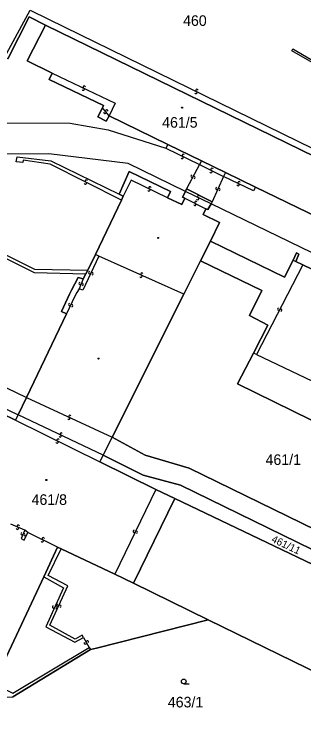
# Model space of a CAD drawing. Extents: x -600309 to -598967, y -1161267 to -1160292.
# Drawn here: x -599975.6 to -599929.1, y -1160957.9 to -1160844.2 of the extents above; entities that cross this region are included whole.
import ezdxf

# ---------------------------------------------------------------- set-up
doc = ezdxf.new("R2010")
doc.units = 0
for name, color, linetype in [('Level 1', 7, 'Continuous'), ('Level 13', 7, 'Continuous'), ('Level 3', 7, 'Continuous'), ('Level 4', 7, 'Continuous'), ('Level 5', 7, 'Continuous'), ('Level 60', 7, 'Continuous')]:
    doc.layers.add(name, color=color, linetype=linetype)

msp = doc.modelspace()

# ---------------------------------------------------------------- linework, layer by layer
at = {"layer": 'Level 1'}
for points in [[(-599970.57, -1160845.99), (-599973.21, -1160844.68), (-599976.65, -1160851.41), (-599979.13, -1160850.22)], [(-599969.49, -1160853.68), (-599973.54, -1160851.74), (-599970.57, -1160845.99)], [(-599922.74, -1160869.32), (-599970.57, -1160845.99)], [(-599969.49, -1160853.68), (-599969.98, -1160854.72), (-599961.24, -1160858.9), (-599961.41, -1160859.24)], [(-599961.41, -1160859.24), (-599962.16, -1160860.72), (-599960.84, -1160861.38), (-599960.35, -1160860.54)], [(-599960.35, -1160860.54), (-599950.92, -1160865.13)], [(-599950.92, -1160865.13), (-599945.53, -1160867.75)], [(-599945.53, -1160867.75), (-599941.67, -1160869.63)], [(-599950.95, -1160873.68), (-599950.5, -1160872.69), (-599957.14, -1160869.49), (-599958.73, -1160873.14)], [(-599941.67, -1160869.63), (-599936.85, -1160871.97)], [(-599948.2, -1160873.77), (-599948.56, -1160873.59), (-599948.1, -1160872.66)], [(-599948.1, -1160872.66), (-599947.91, -1160872.28)], [(-599947.91, -1160872.28), (-599943.8, -1160874.32)], [(-599936.85, -1160871.97), (-599926.79, -1160876.87)], [(-599958.73, -1160873.14), (-599958.07, -1160873.44)], [(-599958.37, -1160874.05), (-599958.07, -1160873.44)], [(-599950.95, -1160873.68), (-599948.66, -1160874.75), (-599948.2, -1160873.77)], [(-599962.53, -1160882.8), (-599958.37, -1160874.05)], [(-599944.79, -1160875.44), (-599944.49, -1160875.59), (-599943.98, -1160874.65)], [(-599943.8, -1160874.32), (-599943.98, -1160874.65)], [(-599944.79, -1160875.44), (-599945.23, -1160876.39), (-599942.61, -1160877.68), (-599944.04, -1160880.67)], [(-599945.66, -1160883.81), (-599944.04, -1160880.67)], [(-599944.04, -1160880.67), (-599932.19, -1160886.44), (-599930.79, -1160883.69)], [(-599963.79, -1160885.29), (-599962.53, -1160882.8)], [(-599930.79, -1160883.69), (-599930.27, -1160882.5), (-599929.85, -1160882.74), (-599930.35, -1160883.89)], [(-599945.66, -1160883.81), (-599948.35, -1160889.16)], [(-599937.18, -1160898.6), (-599934.87, -1160894.12), (-599937.8, -1160892.57), (-599935.84, -1160888.55), (-599945.66, -1160883.81)], [(-599930.35, -1160883.89), (-599929.22, -1160884.43)], [(-599929.22, -1160884.43), (-599901.8, -1160897.62)], [(-599964.52, -1160886.72), (-599964.11, -1160885.91)], [(-599964.11, -1160885.91), (-599963.79, -1160885.29)], [(-599967.22, -1160892.32), (-599968.01, -1160891.94), (-599966.72, -1160889.16), (-599966.38, -1160888.54), (-599965.31, -1160886.46), (-599964.52, -1160886.72)], [(-599948.35, -1160889.16), (-599959.86, -1160912.1)], [(-599973.64, -1160905.73), (-599967.22, -1160892.32)], [(-599912.4, -1160913.66), (-599914.96, -1160912.44), (-599916.27, -1160915.02), (-599939.72, -1160903.54), (-599937.18, -1160898.6)], [(-599988.44, -1160913.35), (-599984.23, -1160905.08), (-599975.42, -1160909.38)], [(-599974.97, -1160908.53), (-599973.64, -1160905.73)], [(-599975.42, -1160909.38), (-599974.97, -1160908.53)], [(-599959.86, -1160912.1), (-599961.32, -1160914.96)], [(-599913.62, -1160933.59), (-599947.48, -1160917.06), (-599954.55, -1160914.98), (-599959.86, -1160912.1)], [(-599961.32, -1160914.96), (-599961.87, -1160916.05)], [(-599961.32, -1160914.96), (-599954.91, -1160918.2), (-599948.9, -1160919.82), (-599908.99, -1160939.27), (-599908.77, -1160939.79), (-599908.72, -1160940.3), (-599908.87, -1160940.9), (-599909.16, -1160941.37)], [(-599961.87, -1160916.05), (-599952.84, -1160920.48)], [(-599952.84, -1160920.48), (-599949.81, -1160921.93)], [(-599949.81, -1160921.93), (-599956.45, -1160935.52)], [(-599909.16, -1160941.37), (-599949.81, -1160921.93)], [(-599983.1, -1160926.22), (-599990.98, -1160942.45), (-599977.66, -1160949), (-599970.85, -1160934.51)], [(-599968.62, -1160929.74), (-599970.85, -1160934.51)], [(-599968.06, -1160930.03), (-599968.62, -1160929.74)], [(-599959.46, -1160934.06), (-599968.06, -1160930.03)], [(-599956.45, -1160935.52), (-599959.46, -1160934.06)], [(-599956.45, -1160935.52), (-599944.44, -1160941.38)], [(-599944.44, -1160941.38), (-599962.39, -1160945.92), (-599963.37, -1160946.18)], [(-599944.44, -1160941.38), (-599883.21, -1160971.22)], [(-599963.37, -1160946.18), (-599975.8, -1160953.73)]]:
    msp.add_lwpolyline(points, dxfattribs=at)
at = {"layer": 'Level 13'}
for centre, start, end in [((-599964.51, -1160856.27), 191.5983, 64.1883), ((-599964.35, -1160855.93), 11.8128, 243.9108), ((-599946.41, -1160856.8), 191.1264, 63.7164), ((-599946.25, -1160856.47), 11.3409, 243.4389), ((-599961.02, -1160860.01), 166.566, 38.664), ((-599960.74, -1160859.77), 346.3516, 218.9416), ((-599948.46, -1160866.89), 11.4514, 243.5494), ((-599948.62, -1160867.23), 191.237, 63.827), ((-599943.83, -1160869.15), 11.5172, 243.6152), ((-599947.04, -1160870.24), 99.4904, 332.0804), ((-599946.72, -1160870.42), 279.7049, 151.8029), ((-599943.99, -1160869.49), 191.3027, 63.8927), ((-599964.18, -1160871.34), 190.7277, 62.8257), ((-599964.02, -1160871.02), 10.5133, 243.1033), ((-599939.63, -1160871.6), 191.4772, 63.5752), ((-599939.47, -1160871.26), 11.2628, 243.8528), ((-599953.96, -1160872.44), 191.6363, 63.7343), ((-599953.8, -1160872.1), 11.4218, 244.0118), ((-599943.05, -1160872.21), 102.7782, 335.3682), ((-599942.71, -1160872.37), 282.9926, 155.0906), ((-599946.12, -1160873.83), 191.5917, 63.6897), ((-599945.96, -1160873.49), 11.3773, 243.9673), ((-599946.58, -1160874.76), 191.0656, 63.6556), ((-599946.42, -1160874.44), 11.2801, 243.3781), ((-599963.46, -1160885.71), 101.6949, 334.2849), ((-599963.12, -1160885.87), 281.9094, 154.0074), ((-599955.25, -1160886.28), 193.2779, 65.3759), ((-599955.09, -1160885.94), 13.0634, 245.6534), ((-599965.03, -1160887.44), 104.1789, 336.7689), ((-599964.69, -1160887.58), 284.3933, 156.4913), ((-599966.69, -1160890.83), 101.0829, 333.6729), ((-599966.37, -1160890.99), 281.2974, 153.3954), ((-599933.1, -1160891.55), 99.8982, 332.4882), ((-599932.78, -1160891.73), 280.1126, 152.2106), ((-599966.83, -1160909.09), 192.3489, 64.9389), ((-599966.67, -1160908.75), 12.5633, 244.6613), ((-599968.56, -1160912.56), 11.164, 243.262), ((-599968.22, -1160911.92), 192.1494, 64.2474), ((-599968.06, -1160911.58), 11.9349, 244.5249), ((-599968.72, -1160912.88), 190.9495, 63.5395), ((-599975.09, -1160926.71), 195.1824, 67.2804), ((-599974.95, -1160926.37), 14.968, 247.558), ((-599956.32, -1160927.19), 101.1699, 333.7599), ((-599955.98, -1160927.35), 281.3844, 153.4823), ((-599974.36, -1160927.59), 102.3289, 334.9189), ((-599974.02, -1160927.75), 282.5434, 154.6414), ((-599970.94, -1160928.4), 11.0237, 243.6137), ((-599971.1, -1160928.72), 191.2381, 63.3361), ((-599969.29, -1160939.32), 102.6453, 335.2353), ((-599968.95, -1160939.48), 282.8597, 154.9577), ((-599968.59, -1160939.04), 102.6494, 334.7474), ((-599968.25, -1160939.2), 282.4349, 155.0249), ((-599964.18, -1160945.12), 156.516, 29.106), ((-599963.86, -1160944.94), 336.7305, 208.8285)]:
    msp.add_arc(centre, 0.184, start, end, dxfattribs=at)
at = {"layer": 'Level 3'}
for points in [[(-599978.86, -1160849.62), (-599976.79, -1160850.51), (-599973.05, -1160843.59), (-599970.08, -1160845.03), (-599922.58, -1160868.23), (-599922.74, -1160869.32)], [(-599903.71, -1160858.37), (-599906.03, -1160862.41), (-599908.54, -1160864.35), (-599911.56, -1160865.31), (-599915.37, -1160865), (-599917.75, -1160863.91), (-599919.98, -1160861.78), (-599921.42, -1160858.95), (-599921.76, -1160855.4), (-599930.98, -1160850.14), (-599930.84, -1160849.79), (-599921.4, -1160855.31), (-599921.03, -1160858.78), (-599919.69, -1160861.49), (-599917.54, -1160863.53), (-599915.28, -1160864.61), (-599911.63, -1160864.89), (-599908.77, -1160863.93), (-599906.44, -1160862.18), (-599904.02, -1160858.22), (-599903.71, -1160858.37)], [(-599969.49, -1160853.68), (-599959.37, -1160858.52), (-599960.35, -1160860.54)], [(-599960.35, -1160860.54), (-599961.41, -1160859.24)], [(-599996.04, -1160861.66), (-599966.59, -1160861.72), (-599960.5, -1160862.77), (-599951.23, -1160865.76)], [(-599950.92, -1160865.13), (-599951.23, -1160865.76)], [(-599951.23, -1160865.76), (-599945.86, -1160868.37)], [(-599948.1, -1160872.66), (-599957.28, -1160868.22), (-599961.7, -1160867.66), (-599970.05, -1160866.64), (-599988.92, -1160866.68), (-599996.2, -1160866.35)], [(-599958.37, -1160874.05), (-599969.83, -1160868.3), (-599974.17, -1160867.64), (-599974.19, -1160868.01), (-599975.26, -1160867.95), (-599975.1, -1160867.13), (-599969.7, -1160867.76), (-599958.73, -1160873.14)], [(-599945.53, -1160867.75), (-599945.86, -1160868.37)], [(-599945.86, -1160868.37), (-599947.91, -1160872.28)], [(-599945.86, -1160868.37), (-599941.96, -1160870.26)], [(-599941.96, -1160870.26), (-599943.8, -1160874.32)], [(-599941.67, -1160869.63), (-599941.96, -1160870.26)], [(-599936.85, -1160871.97), (-599937.14, -1160872.6), (-599941.96, -1160870.26)], [(-600000.37, -1160871.12), (-599972.33, -1160885.16), (-599963.79, -1160885.29)], [(-599950.95, -1160873.68), (-599956.8, -1160870.86), (-599958.07, -1160873.44)], [(-600000.57, -1160871.58), (-599972.42, -1160885.7), (-599964.11, -1160885.91)], [(-599943.98, -1160874.65), (-599948.1, -1160872.66)], [(-599948.2, -1160873.77), (-599944.79, -1160875.44)], [(-599900.78, -1160895.55), (-599943.98, -1160874.65)], [(-599961.99, -1160883.06), (-599962.53, -1160882.8)], [(-599961.99, -1160883.06), (-599964.59, -1160888.52), (-599965.19, -1160888.3)], [(-599948.35, -1160889.16), (-599961.99, -1160883.06)], [(-599930.79, -1160883.69), (-599930.35, -1160883.89)], [(-599929.22, -1160884.43), (-599936.65, -1160898.85)], [(-599964.52, -1160886.72), (-599965.19, -1160888.3)], [(-599965.19, -1160888.3), (-599965.54, -1160888.89), (-599965.84, -1160889.5), (-599967.22, -1160892.32)], [(-600000.71, -1160892.71), (-599973.64, -1160905.73)], [(-599936.65, -1160898.85), (-599937.18, -1160898.6)], [(-599936.65, -1160898.85), (-599911.12, -1160910.96)], [(-599985.37, -1160903.56), (-599974.97, -1160908.53)], [(-599973.64, -1160905.73), (-599959.86, -1160912.1)], [(-599961.32, -1160914.96), (-599974.97, -1160908.53)], [(-599975.42, -1160909.38), (-599961.87, -1160916.05)], [(-599952.84, -1160920.48), (-599959.46, -1160934.06)], [(-599973.88, -1160927), (-599976.16, -1160926.07)], [(-599973.88, -1160927), (-599974.5, -1160928.34), (-599973.99, -1160928.63), (-599973.43, -1160927.38)], [(-599973.43, -1160927.38), (-599973.88, -1160927)], [(-599968.62, -1160929.74), (-599973.43, -1160927.38)], [(-599964.47, -1160944.23), (-599964.67, -1160943.86), (-599965.83, -1160944.51), (-599969.87, -1160942.28), (-599966.96, -1160935.96), (-599970.13, -1160934.31), (-599968.06, -1160930.03)], [(-599970.85, -1160934.51), (-599967.69, -1160936.27), (-599970.54, -1160942.52), (-599965.88, -1160945), (-599964.47, -1160944.23)], [(-599998.29, -1160938.28), (-599996.71, -1160943.04), (-599975.82, -1160953.17), (-599963.57, -1160945.83)], [(-599964.47, -1160944.23), (-599963.57, -1160945.83)], [(-599963.57, -1160945.83), (-599963.37, -1160946.18)]]:
    msp.add_lwpolyline(points, dxfattribs=at)
at = {"layer": 'Level 5'}
msp.add_line((-599948.37, -1160951.65), (-599947.49, -1160951.65), dxfattribs=at)
for centre, radius in [((-599948.63, -1160859.23), 0.09), ((-599948.63, -1160859.23), 0.0521), ((-599952.46, -1160880.13), 0.09), ((-599952.46, -1160880.13), 0.0521), ((-599962.06, -1160899.49), 0.09), ((-599962.06, -1160899.49), 0.0521), ((-599970.43, -1160918.97), 0.09), ((-599970.43, -1160918.97), 0.0521), ((-599948.37, -1160951.27), 0.375)]:
    msp.add_circle(centre, radius, dxfattribs=at)
at = {"layer": 'Level 60'}
for points in [[(-599929.66, -1160840.77), (-599912.31, -1160849.72), (-599901.15, -1160855.51), (-599899.04, -1160856.57), (-599887.1, -1160862.89), (-599885.05, -1160863.95), (-599877.9, -1160867.65), (-599883.62, -1160881.94), (-599899.05, -1160876.78), (-599915.43, -1160876.17), (-599918.37, -1160876.66), (-599921.45, -1160877.01), (-599926.79, -1160876.87), (-599922.74, -1160869.32), (-599970.57, -1160845.99), (-599973.21, -1160844.68), (-599976.65, -1160851.41), (-599979.13, -1160850.22), (-599980.31, -1160849.65), (-599989.34, -1160845.43), (-599988.23, -1160842.67)], [(-599976.65, -1160851.41), (-599973.21, -1160844.68), (-599970.57, -1160845.99), (-599973.54, -1160851.74), (-599969.49, -1160853.68), (-599969.98, -1160854.72), (-599961.24, -1160858.9), (-599961.41, -1160859.24), (-599962.16, -1160860.72), (-599960.84, -1160861.38), (-599960.35, -1160860.54), (-599950.92, -1160865.13), (-599945.53, -1160867.75), (-599941.67, -1160869.63), (-599936.85, -1160871.97), (-599926.79, -1160876.87)], [(-599984.23, -1160905.08), (-599975.42, -1160909.38), (-599974.97, -1160908.53), (-599973.64, -1160905.73), (-599967.22, -1160892.32), (-599968.01, -1160891.94), (-599966.72, -1160889.16), (-599966.38, -1160888.54), (-599965.31, -1160886.46), (-599964.52, -1160886.72), (-599964.11, -1160885.91), (-599963.79, -1160885.29), (-599962.53, -1160882.8), (-599958.37, -1160874.05), (-599958.07, -1160873.44), (-599958.73, -1160873.14), (-599957.14, -1160869.49), (-599950.5, -1160872.69), (-599950.95, -1160873.68), (-599948.66, -1160874.75), (-599948.2, -1160873.77), (-599948.56, -1160873.59), (-599948.1, -1160872.66), (-599947.91, -1160872.28), (-599943.8, -1160874.32), (-599943.98, -1160874.65), (-599944.49, -1160875.59), (-599944.79, -1160875.44), (-599945.23, -1160876.39), (-599942.61, -1160877.68), (-599944.04, -1160880.67), (-599945.66, -1160883.81), (-599948.35, -1160889.16), (-599959.86, -1160912.1), (-599961.32, -1160914.96), (-599961.87, -1160916.05), (-599952.84, -1160920.48), (-599949.81, -1160921.93), (-599956.45, -1160935.52), (-599959.46, -1160934.06), (-599968.06, -1160930.03), (-599968.62, -1160929.74), (-599970.85, -1160934.51), (-599977.66, -1160949)], [(-599901.8, -1160897.62), (-599929.22, -1160884.43), (-599930.35, -1160883.89), (-599929.85, -1160882.74), (-599930.27, -1160882.5), (-599930.79, -1160883.69), (-599932.19, -1160886.44), (-599944.04, -1160880.67), (-599942.61, -1160877.68), (-599945.23, -1160876.39), (-599944.79, -1160875.44), (-599944.49, -1160875.59), (-599943.98, -1160874.65), (-599943.8, -1160874.32), (-599947.91, -1160872.28), (-599948.1, -1160872.66), (-599948.56, -1160873.59), (-599948.2, -1160873.77), (-599948.66, -1160874.75), (-599950.95, -1160873.68), (-599950.5, -1160872.69), (-599957.14, -1160869.49), (-599958.73, -1160873.14), (-599958.07, -1160873.44), (-599958.37, -1160874.05), (-599962.53, -1160882.8), (-599963.79, -1160885.29), (-599964.11, -1160885.91), (-599964.52, -1160886.72), (-599965.31, -1160886.46), (-599966.38, -1160888.54), (-599966.72, -1160889.16), (-599968.01, -1160891.94), (-599967.22, -1160892.32)], [(-599916.27, -1160915.02), (-599939.72, -1160903.54), (-599937.18, -1160898.6), (-599934.87, -1160894.12), (-599937.8, -1160892.57), (-599935.84, -1160888.55), (-599945.66, -1160883.81), (-599944.04, -1160880.67), (-599932.19, -1160886.44), (-599930.79, -1160883.69), (-599930.27, -1160882.5), (-599929.85, -1160882.74), (-599930.35, -1160883.89), (-599929.22, -1160884.43), (-599901.8, -1160897.62)], [(-599913.62, -1160933.59), (-599947.48, -1160917.06), (-599954.55, -1160914.98), (-599959.86, -1160912.1), (-599948.35, -1160889.16), (-599945.66, -1160883.81), (-599935.84, -1160888.55), (-599937.8, -1160892.57), (-599934.87, -1160894.12), (-599937.18, -1160898.6), (-599939.72, -1160903.54), (-599916.27, -1160915.02)], [(-599967.22, -1160892.32), (-599973.64, -1160905.73), (-599974.97, -1160908.53), (-599975.42, -1160909.38), (-599984.23, -1160905.08)], [(-599977.66, -1160949), (-599970.85, -1160934.51), (-599968.62, -1160929.74), (-599968.06, -1160930.03), (-599959.46, -1160934.06), (-599956.45, -1160935.52), (-599944.44, -1160941.38), (-599962.39, -1160945.92), (-599963.37, -1160946.18), (-599975.8, -1160953.73)], [(-600019.43, -1160960.81), (-600016.81, -1160953.62), (-600013.23, -1160955.09), (-599975.8, -1160953.73), (-599963.37, -1160946.18), (-599962.39, -1160945.92), (-599944.44, -1160941.38), (-599883.21, -1160971.22)]]:
    msp.add_lwpolyline(points, dxfattribs=at)
for points in [[(-599922.74, -1160869.32), (-599926.79, -1160876.87), (-599936.85, -1160871.97), (-599941.67, -1160869.63), (-599945.53, -1160867.75), (-599950.92, -1160865.13), (-599960.35, -1160860.54), (-599960.84, -1160861.38), (-599962.16, -1160860.72), (-599961.41, -1160859.24), (-599961.24, -1160858.9), (-599969.98, -1160854.72), (-599969.49, -1160853.68), (-599973.54, -1160851.74), (-599970.57, -1160845.99)], [(-599878.88, -1160950.53), (-599879.52, -1160953.57), (-599902.42, -1160942.44), (-599902.98, -1160942.33), (-599903.48, -1160942.44), (-599903.86, -1160942.65), (-599904.14, -1160942.96), (-599904.35, -1160943.38), (-599904.4, -1160943.7), (-599909.16, -1160941.37), (-599908.87, -1160940.9), (-599908.72, -1160940.3), (-599908.77, -1160939.79), (-599908.99, -1160939.27), (-599948.9, -1160919.82), (-599954.91, -1160918.2), (-599961.32, -1160914.96), (-599959.86, -1160912.1), (-599954.55, -1160914.98), (-599947.48, -1160917.06), (-599913.62, -1160933.59), (-599908, -1160936.27)], [(-599909.16, -1160941.37), (-599949.81, -1160921.93), (-599952.84, -1160920.48), (-599961.87, -1160916.05), (-599961.32, -1160914.96), (-599954.91, -1160918.2), (-599948.9, -1160919.82), (-599908.99, -1160939.27), (-599908.77, -1160939.79), (-599908.72, -1160940.3), (-599908.87, -1160940.9)], [(-599949.81, -1160921.93), (-599909.16, -1160941.37), (-599904.4, -1160943.7), (-599879.91, -1160955.44), (-599871, -1160959.71), (-599871.36, -1160961.41), (-599877.5, -1160974), (-599883.21, -1160971.22), (-599944.44, -1160941.38), (-599956.45, -1160935.52)]]:
    msp.add_lwpolyline(points, close=True, dxfattribs=at)

# ---------------------------------------------------------------- texts
at = {"layer": 'Level 4'}
for s, p in [('460', (-599948.47, -1160846.12)), ('461/5', (-599951.83, -1160862.45)), ('461/1', (-599935.22, -1160916.55)), ('461/8', (-599972.81, -1160922.96)), ('463/1', (-599950.92, -1160955.45))]:
    msp.add_text(s, height=1.7, dxfattribs=at).set_placement(p)
msp.add_text('461/11', height=1.2, rotation=334.8, dxfattribs=at).set_placement((-599934.39, -1160928.86))

doc.saveas('drawing.dxf')
